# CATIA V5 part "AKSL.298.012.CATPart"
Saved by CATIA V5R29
Part number: АКСЛ.298.012
Definition: Уголок 200 мм
Publications: "Грань по длине шипа", "Грань по ширине шипа", "Грань по длине шипа1", "Грань по ширине шипа1"
Material "Steel": density 7860 kg/m3, Young's modulus 2e+11 Pa, Poisson ratio 0.266, thermal expansion 1.17e-05 1/K
Bounding box of the stored display mesh (mm): x -52 to 51, y -51 to 52, z -103 to 100
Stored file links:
  Z:\ООО Аксель\Соединения бруса\Соединения бруса\Соединения из листа\АКСЛ.298.010 (Основание)\AKSL.298.012.CATPart
  Z:\ООО Аксель\Соединения бруса\Соединения бруса\Соединения из листа\АКСЛ.298.010 (Основание)\AKSL.298.010.CATProduct
  Z:\#Catalog_GosNIIAS\Holes&Pockets\Part\Соединение шип-паз\Ship-Paz.CATPart
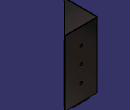
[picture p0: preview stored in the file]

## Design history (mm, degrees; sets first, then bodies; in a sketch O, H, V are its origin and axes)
External parameters (linked from other documents)
  `External.S металла` = 2 mm
  `External.R гиба` = 1.9 mm
  `External.K-factor` = 0.49
SheetMetalParameters1: Thickness 2 {= `External.S металла`}, BendRadius 1.9 {= `External.R гиба`}, KFactor 0.49 {= `External.K-factor`}, ReliefRadialLength 1, ReliefAxialLength 2, MinimumBendRadius 0
Set1 "Шип в центре грани"
  Extract1 "Плоскость шипа": ExtractElem face of Wall2
  Extract2 "Грань по длине шипа": ExtractElem edge of Extract1
  Extract3 "Грань по ширине шипа": ExtractElem edge of Extract1
Set2 "Шип в центре грани"
  Extract4 "Плоскость шипа": ExtractElem face of Wall1
  Extract5 "Грань по длине шипа": ExtractElem edge of Extract4
  Extract6 "Грань по ширине шипа": ExtractElem edge of Extract4
Set3
  DatumCurve1: linked copy from another document
  Plane1: linked copy from another document
Body1 (main body)
  Pad1: profile DatumCurve1, length 203, opposite side length -3, thin wall 0, second thickness 2 {= `External.S металла`}
  Sketch1 on face of Pad1, origin (0, 52, 153), H (1, 0, 0), V (0, 0, -1)
    point P1 (0, 103)
    reference projected point E1 (0, 103) from Sketch3.P7
    coincidence: E1 P1
  Hole1: placed by Sketch1, at (0, 52, 50) direction (0, -1, 0), diameter 8, through (limit type 6)
  RectPattern1: of Hole1, direction 1 instances 3, spacing 50, along edge [face of Pad1 | face of Pad1] reversed
  Recognize1: Recognize_BendTable SheetMetalParameters1, Recognize_ReferenceFace face of Pad1, Recognize_BendDefaultRadius 1.9 {= `External.R гиба`}, KFacteur 0.49 {= SheetMetalParameters1.KFactor}
  d_Bend1: Bend_BendTable SheetMetalParameters1, Bend_Thickness 2 {= `External.S металла`}, Bend_KFactor 0.49 {= SheetMetalParameters1.KFactor}, Bend_FirstSupport face of Recognize1, Bend_SecondSupport face of Recognize1, Bend_KFactorRadius 1.9 {= d_Bend1.CylindricalBendSurf_Radius}, Bend_Deduction -3.2761 {= (d_Bend1.CylindricalBendSurf_Radius+SheetMetalParameters1.Thickness*d_Bend1.Bend_KFactor)*(PI-abs(d_Bend1.BendSurf_OpenAngle))-2*(d_Bend1.CylindricalBendSurf_Radius+SheetMetalParameters1.Thickness)*tan(min((PI-abs(d_Bend1.BendSurf_OpenAngle)),(PI/2))/2)}
  Wall1: Thickness 2 {= `External.S металла`}, Profile Sketch4, ListTangentTo face of Recognize1, OffsetValue 0
  Sketch2 on face of Recognize1, origin (-52, -52, -103), H (0, 1, 0), V (0, 0, 1)
    line L1 (0, 203) -> (1, 203)
    line L2 (1, 203) -> (1, 193.5)
    line L3 (1, 193.5) -> (2, 193.5)
    line L4 (2, 193.5) -> (2, 12.5)
    line L5 (2, 12.5) -> (1, 12.5)
    line L6 (1, 12.5) -> (1, 3)
    line L7 (1, 3) -> (0, 3)
    line L8 (0, 3) -> (0, 203)
    distance L8 L2 = 1
    distance L4 L8 = 2 {= `External.S металла`}
    distance L1 L3 = 9.5
    distance L5 L7 = 9.5
    horizontal: L1 H, L3 H, L5 H, L7 H
    vertical: L2 V, L4 V, L6 V, L8 V
    coincidence: L6 L2
  CutOut1: Direction Sketch2, EndLimit through (limit type 2), Orientation false, Profile Sketch2, StartLimit through (limit type 2), Thickness1 2, Thickness2 2
  Wall2: Thickness 2 {= `External.S металла`}, Profile Sketch5, ListTangentTo face of Recognize1, OffsetValue 0
  Sketch3 on face of Pad1, origin (0, 52, 0), H (-1, 0, 0), V (0, 0, 1)
    construction line L1 (0, -14) -> (0, 221)
    point P5 (0, -14)
    point P6 (0, 221)
    point P7 (0, 50)
    construction line L2 (-50, 100) -> (52, 100)
    distance L2 P7 = 50
    coincidence: P5 V, P6 V, P7 L1
    vertical: L1 V
    horizontal: L2 H
  Sketch4 on face of Recognize1, origin (-52, 52, 0), H (-1, 0, 0), V (0, 0, 1)
    reference projected line E1 (-102, -100) -> (-102, 100) from edge [face of Recognize1 | face of Recognize1]
    line L1 (-103, 90) -> (-102, 90)
    line L2 (-102, 90) -> (-102, -90)
    line L3 (-102, -90) -> (-103, -90)
    line L4 (-103, -90) -> (-103, 90)
    axis line L5 (-102, 0) -> (-103, 0)
    point P7 (-102, 0)
    point P8 (-103, 0)
    distance L2 L4 = 1
    distance L1 L3 = 180
    length E1 = 200 (reference)
    perpendicularity: L2 L1
    midpoint: P7 L2, P8 L4, P7 E1
    coincidence: L2 E1
  Sketch5 on face of Recognize1, origin (-52, 52, 0), H (-1, 0, 0), V (0, 0, 1)
    reference projected line E1 (-3.9, -100) -> (-102, -100) from edge [face of Recognize1 | face of Recognize1]
    line L1 (-77, -103) -> (-77, -100)
    line L2 (-77, -100) -> (-27, -100)
    line L3 (-27, -100) -> (-27, -103)
    line L4 (-27, -103) -> (-77, -103)
    axis line L5 (-52, -100.2136) -> (-52, -103.2213)
    reference projected line E2 (0, -100) -> (0, 100) from edge [face of Recognize1 | face of d_Bend1]
    construction line L6 (-4, -100) -> (0, -100)
    point P11 (-4, -100)
    construction line L7 (-102, -100) -> (-102, -76)
    distance L2 L4 = 3 {= `External.S металла` +1mm}
    distance L1 L3 = 50
    length E1 = 98.1 (reference)
    distance L3 E2 = 27
    perpendicularity: L2 L1
    coincidence: L2 E1, P11 E1
    horizontal: L6 H
    vertical: L7 V, L5 V
    symmetry: L1 L3 L5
